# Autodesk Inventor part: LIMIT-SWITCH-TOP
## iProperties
Created: 2007-08
Part Number: LIMIT-SWITCH-TOP
Material: ABS Plastic
Document SubType Name: Modeling
Density: 1.06 g/cm^3
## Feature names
1. Base1
